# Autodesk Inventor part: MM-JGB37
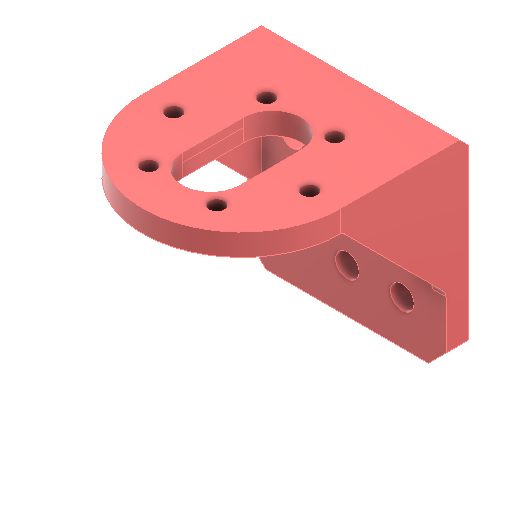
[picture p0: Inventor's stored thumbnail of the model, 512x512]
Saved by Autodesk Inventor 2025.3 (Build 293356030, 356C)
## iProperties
Created: 2024-01
Part Number: MM-JGB37
Material: Plastica ABS
Document SubType Name: Modeling
Designer: R5800u
Density: 1.06 g/cm^3
Appearance: Liscia - Rosso
Sending System: Autodesk Translation Framework v12.14.0.127
Preprocessor: ST-DEVELOPER v20
Title: MM-JGB37 v4.step
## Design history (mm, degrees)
node "Body1"
sketch "Schizzo1"
  geometry: L1 (0, -42.5)-(0, 0) reference; L2 (40, -42.5)-(0, -42.5) reference; L3 (40, -42.5)-(40, 0) reference; L4 (0, 0)-(40, 0) reference; 1 further point
extrude "Estrusione1" join sketch "Schizzo1" distance "d0" = 2; taper "d1" = 0 deg
sketch "Schizzo3"
  geometry: L1 (20, 0)-(20, 29) reference; L2 (-20, 29)-(20, 29) reference; L3 (-20, 29)-(-20, 0) reference; L4 (-6.5, -7)-(-6.5, 7) reference; L5 (6.5, 7)-(6.5, -7) reference; C1 r 1.75 at (15.5, 0) reference; C2 r 1.75 at (-7.75, -13.423) reference; C3 r 1.75 at (7.75, -13.423) reference; C4 r 1.75 at (7.75, 13.423) reference; C5 r 1.75 at (-15.5, 0) reference; C6 r 1.75 at (-7.75, 13.423) reference; A1 r 20 centre (0, 0) between (-20, 0) and (20, 0) reference; A2 r 6.5 centre (0, 7) between (6.5, 7) and (-6.5, 7) reference; A3 r 6.5 centre (0, -7) between (-6.5, -7) and (6.5, -7) reference; 1 further point
extrude "Estrusione2" join sketch "Schizzo3" distance "d2" = 2; taper "d3" = 0 deg
sketch "Schizzo5"
  geometry: L1 (20, 0)-(20, 29) reference; L2 (20, 29)-(-20, 29) reference; L3 (-20, 29)-(-20, 0) reference; L4 (6.5, 7)-(6.5, -7) reference; L5 (-6.5, -7)-(-6.5, 7) reference; L6 (-22.5, 0)-(-22.5, 31.5); L7 (-22.5, 31.5)-(22.5, 31.5); L8 (22.5, 31.5)-(22.5, 0); L9 (22.5, 29)-(20, 29); L10 (-22.5, 29)-(-20, 29); C1 r 1.75 at (-7.75, 13.423) reference; C2 r 1.75 at (-15.5, 0) reference; C3 r 1.75 at (7.75, 13.423) reference; C4 r 1.75 at (7.75, -13.423) reference; C5 r 1.75 at (-7.75, -13.423) reference; C6 r 1.75 at (15.5, 0) reference; A1 r 20 centre (0, 0) between (-20, 0) and (20, 0) reference; A2 r 6.5 centre (0, -7) between (-6.5, -7) and (6.5, -7) reference; A3 r 6.5 centre (0, 7) between (6.5, 7) and (-6.5, 7) reference; A4 r 22.5 centre (0, 0) between (-22.5, 0) and (22.5, 0); 1 further point
  constraints: 10 end point, 3 point on line, 2 perpendicular, 2 point on circle, 1 centre point, 3 other
  dimensions: "d5" = 2.5 radial gap between concentric circles of A1 A4
extrude "Estrusione3" join sketch "Schizzo5" stored distance "d6" = 2; taper "d7" = 0 deg
sketch "Schizzo6"
  geometry: L1 (-2.5, -5)-(-2.5, 24) reference; L2 (42.5, 24)-(42.5, -5) reference; L3 (-2.5, -5)-(42.5, -5); L4 (42.5, -5)-(42.5, 0); L5 (42.5, 0)-(-2.5, 0); L6 (-2.5, 0)-(-2.5, -5); L7 (0, 0)-(40, 0) reference; L8 (0, -5)-(0, 0) reference; L9 (40, -5)-(0, -5) reference; L10 (40, -5)-(40, 0) reference; 3 further points
  constraints: 8 end point, 2 parallel, 2 point on line, 1 horizontal, 1 perpendicular
extrude "Estrusione4" join sketch "Schizzo6" stored distance "d8" = 10; taper "d9" = 0 deg
sketch "Schizzo7"
  geometry: L1 (5, -5)-(29, -5) reference; L2 (29, 0)-(29, -5) reference; L3 (0, 0)-(29, 0) reference; L4 (0, 0)-(0, -44.5) reference; L5 (5, -44.5)-(0, -44.5) reference; L6 (5, -44.5)-(5, -5) reference; L7 (27.973, -5.631)-(5, -28.604); A1 r 1.151 centre (29, -6.151) between (29, -5) and (27.973, -5.631); 1 further point
  constraints: 2 end point, 2 point on circle, 1 centre point, 1 point on line, 1 tangent
  dimensions: "d10" = 45 deg angle of L6 L7
extrude "Estrusione5" join sketch "Schizzo7" distance "d11" = 3; taper "d12" = 0 deg
node "Piano di lavoro1"
mirror "Speculare1"
fillet "Raccordo1" dims "d13" = 2
sketch "Schizzo8"
  geometry: L1 (10, -180.5)-(10, 19.5) reference; L2 (0, 29.5)-(300, 29.5) reference; L3 (45, 0)-(0, 0) reference; L4 (45, 0)-(45, 15.067) reference; L5 (0, 16.481)-(0, 38.869) reference; L6 (0, 0)-(0, 15.067) reference; 8 further points
  constraints: 4 point on line, 1 midpoint
  dimensions: "d16" = 10 distance from line of L3 point (10, 10); "d17" = 10 distance from line of L4 point (35, 29.5); "d18" = 12.5 distance of point (35, 29.5) point (22.5, 29.5); "d29" = 10.00001 distance from line of L5 point (10, 29.5); "d30" = 45 distance from line of point (0, 7.534) L4 (derived)
  node "Riferimento1"
  node "Riferimento2"
hole "Foro1" sketch "Schizzo8" diameter "d19" = 5.3; stored, may be unused: countersink angle "d23" = 89.9544 deg, drill point angle "d25" = 118 deg; dims "d20" = 6, "d21" = 9.4, "d22" = 2, "d24" = 8
chamfer "Smusso1" distance "d26" = 4; stored, may be unused: second distance "d27" = 2, angle "d28" = 45 deg
chamfer "Smusso2" distance "d31" = 2; stored, may be unused: second distance "d32" = 2, angle "d33" = 45 deg
node "Solido1"
node "Linea chiusa proiettata1"
node "Linea chiusa proiettata2"
node "Linea chiusa proiettata3"
node "Linea chiusa proiettata4"
node "Linea chiusa proiettata5"
